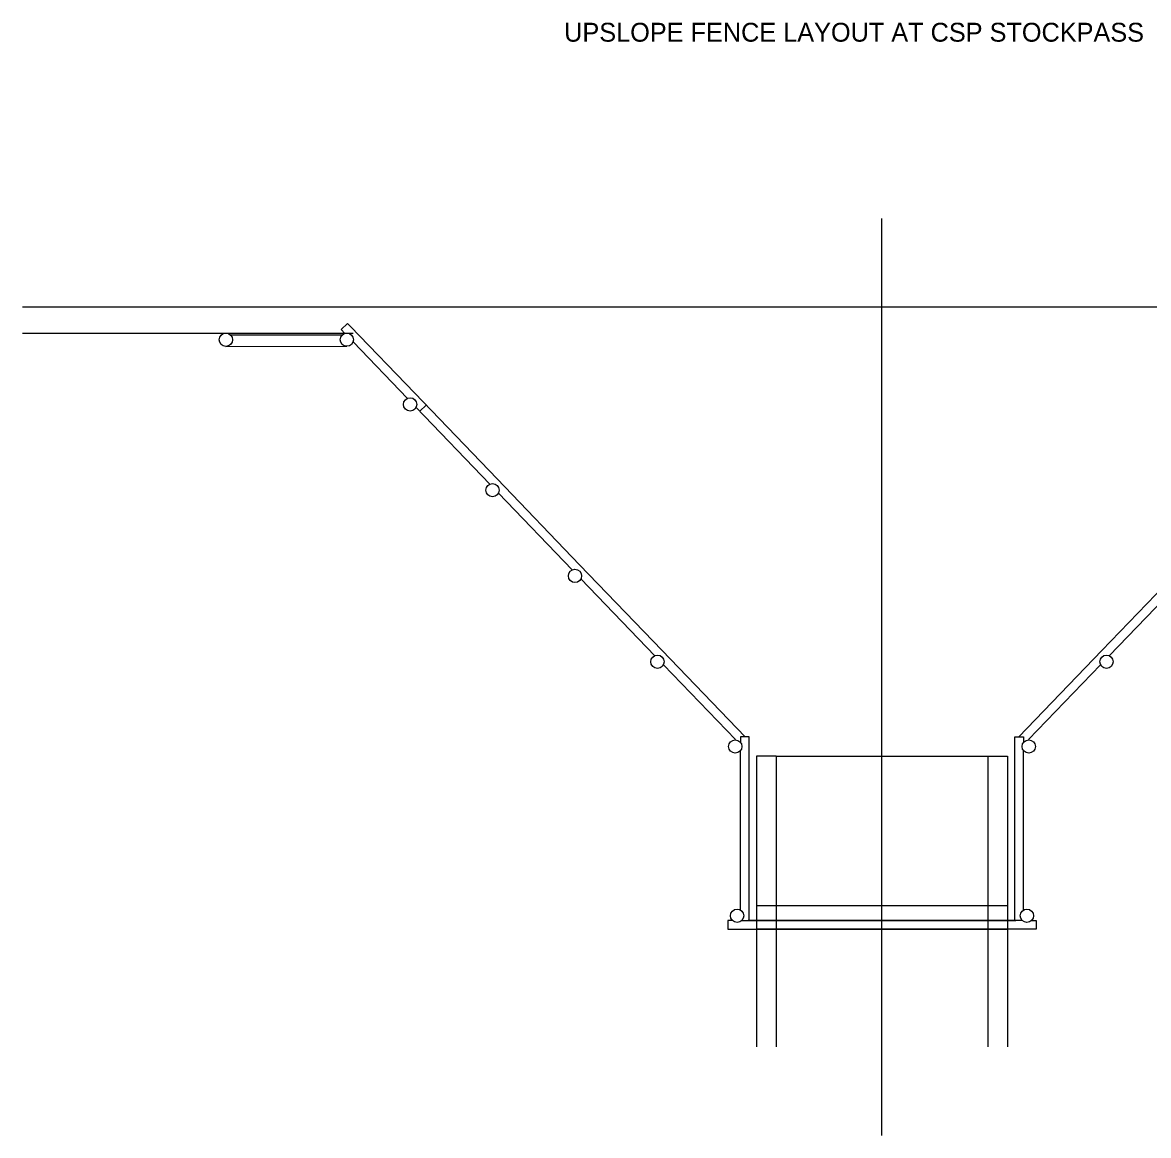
# Model space of a CAD drawing. Extents: x 49991 to 50288, y 49919 to 50011.
# Drawn here: x 50059.75 to 50102.33, y 49945.64 to 49987.75 of the extents above; entities that cross this region are included whole.
import ezdxf

# ---------------------------------------------------------------- set-up
doc = ezdxf.new("R2010")
doc.units = 0
for name, color, linetype in [('Level 1', 7, 'Continuous'), ('Level 2', 7, 'Continuous'), ('Level 5', 7, 'Continuous'), ('Level 7', 7, 'Continuous')]:
    doc.layers.add(name, color=color, linetype=linetype)

msp = doc.modelspace()

# ---------------------------------------------------------------- linework, layer by layer
at = {"layer": 'Level 1'}
for p, q in [((50059.753, 49976.996), (50124.756, 49976.996)), ((50059.756, 49975.996), (50072.256, 49975.996)), ((50067.609, 49975.936), (50071.852, 49975.936)), ((50067.444, 49975.495), (50072.019, 49975.497)), ((50088.256, 49959.996), (50087.506, 49959.996)), ((50087.506, 49959.996), (50087.506, 49959.686)), ((50088.256, 49959.996), (50088.256, 49948.996)), ((50088.256, 49959.996), (50096.256, 49959.996)), ((50096.256, 49959.996), (50096.256, 49948.996)), ((50096.256, 49959.996), (50097.006, 49959.996)), ((50097.006, 49959.996), (50097.006, 49959.686)), ((50087.506, 49959.686), (50087.506, 49948.996)), ((50097.006, 49959.686), (50097.006, 49948.996)), ((50087.506, 49954.341), (50097.006, 49954.341))]:
    msp.add_line(p, q, dxfattribs=at)
at = {"layer": 'Level 5'}
msp.add_line((50092.256, 49945.642), (50092.256, 49980.329), dxfattribs=at)
at = {"layer": 'Level 7'}
for p, q in [((50071.804, 49976.132), (50072.046, 49976.365)), ((50072.046, 49976.365), (50072.159, 49976.247)), ((50072.159, 49976.247), (50074.584, 49973.724)), ((50071.943, 49975.988), (50071.804, 49976.132)), ((50072.256, 49975.662), (50074.306, 49973.528)), ((50074.584, 49973.724), (50077.702, 49970.48)), ((50074.635, 49973.186), (50077.424, 49970.284)), ((50074.635, 49973.186), (50074.773, 49973.042)), ((50074.773, 49973.042), (50075.015, 49973.275)), ((50077.702, 49970.48), (50080.82, 49967.235)), ((50077.753, 49969.942), (50080.542, 49967.039)), ((50080.82, 49967.235), (50083.938, 49963.99)), ((50103.693, 49967.235), (50100.575, 49963.99)), ((50080.871, 49966.697), (50083.66, 49963.794)), ((50103.642, 49966.697), (50100.853, 49963.794)), ((50083.938, 49963.99), (50087.076, 49960.725)), ((50100.575, 49963.99), (50097.437, 49960.725)), ((50083.989, 49963.452), (50086.712, 49960.618)), ((50100.524, 49963.452), (50097.8, 49960.618)), ((50087.237, 49960.725), (50086.902, 49960.725)), ((50086.902, 49960.725), (50086.902, 49960.518)), ((50087.237, 49953.78), (50087.237, 49960.725)), ((50097.275, 49953.78), (50097.275, 49960.725)), ((50097.275, 49960.725), (50097.611, 49960.725)), ((50097.611, 49960.725), (50097.611, 49960.518)), ((50086.902, 49954.144), (50086.902, 49960.199)), ((50097.611, 49954.144), (50097.611, 49960.199)), ((50086.598, 49953.78), (50086.425, 49953.78)), ((50086.425, 49953.78), (50086.425, 49953.444)), ((50086.954, 49953.78), (50097.314, 49953.78)), ((50097.559, 49953.78), (50087.199, 49953.78)), ((50097.914, 49953.78), (50098.088, 49953.78)), ((50098.088, 49953.78), (50098.088, 49953.444)), ((50086.425, 49953.444), (50097.02, 49953.444)), ((50098.088, 49953.444), (50087.492, 49953.444))]:
    msp.add_line(p, q, dxfattribs=at)
for centre in [(50067.444, 49975.746), (50072.019, 49975.748), (50074.41, 49973.3), (50077.528, 49970.055), (50080.646, 49966.81), (50083.764, 49963.565), (50100.748, 49963.565), (50086.707, 49960.358), (50097.805, 49960.358), (50086.776, 49953.957), (50097.737, 49953.957)]:
    msp.add_circle(centre, 0.251, dxfattribs=at)

# ---------------------------------------------------------------- texts
at = {"layer": 'Level 2'}
msp.add_text('UPSLOPE FENCE LAYOUT AT CSP STOCKPASS', height=0.71452, dxfattribs=at).set_placement((50080.237, 49987.022))

doc.saveas('drawing.dxf')
